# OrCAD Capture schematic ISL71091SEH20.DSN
size A
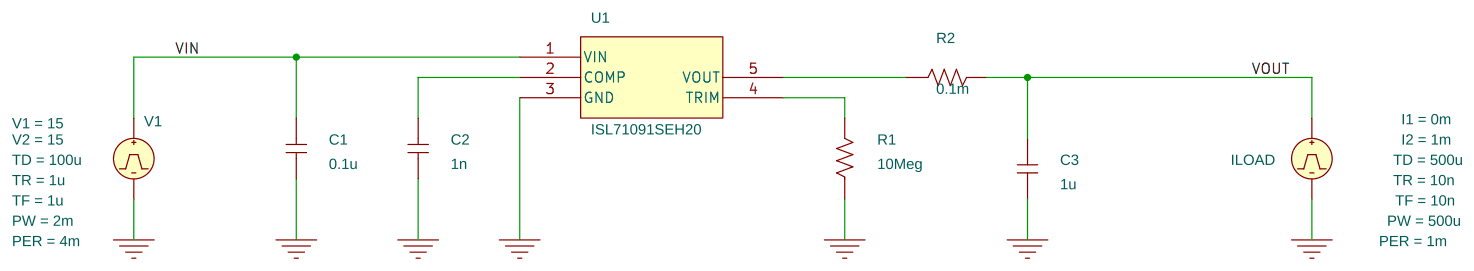
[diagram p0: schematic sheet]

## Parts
C1  0.1u  [RAD/CK05]
C2  1n  [RAD/CK05]
C3  1u  [RAD/CK05]
ILOAD  IPULSE
R1  10Meg  [AX/RC05]
R2  0.1m  [AX/RC05]
U1  ISL71091SEH20
V1  VPULSE

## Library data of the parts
C1-C3 = C
ILOAD = IPULSE: I1: 0m; I2: 1m; PER: 1m; PW: 500u; TD: 500u; TF: 10n; TR: 10n
R1 R2 = R
U1 = ISL71091SEH20_0
V1 = VPULSE: PER: 4m; PW: 2m; TD: 100u; TF: 1u; TR: 1u; V1: 15; V2: 15

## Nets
VIN: C1.2 U1.1(VIN) V1.1(+)
0: C1.1 C2.1 C3.1 ILOAD.2(-) R1.1 U1.3(GND) V1.2(-)
VOUT: C3.2 ILOAD.1(+) R2.2
N14648: C2.2 U1.2(COMP)
N14863: R1.2 U1.4(TRIM)
N15000: R2.1 U1.5(VOUT)
